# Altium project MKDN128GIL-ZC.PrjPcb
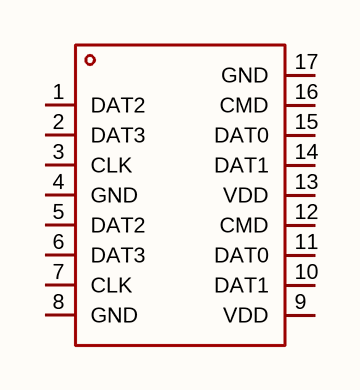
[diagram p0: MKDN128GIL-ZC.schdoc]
1 sheet, 1 parts. Net scope: global (net labels, ports and power ports of the same name join across sheets).

## Sheet MKDN128GIL-ZC.schdoc
size 127 x 101 mm

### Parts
U?  mkdn128gil-zc  [LGA-16_L13.0-W9.0_MKDN128GIL-ZC]  (value not drawn)

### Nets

Not connected (* = marked no-connect by the designer): U? 1(DAT2) 2(DAT3) 3(CLK) 4(GND) 5(DAT2) 6(DAT3) 7(CLK) 8(GND) 9(VDD) 10(DAT1) 11(DAT0) 12(CMD) 13(VDD) 14(DAT1) 15(DAT0) 16(CMD) 17(GND)

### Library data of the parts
U? = mkdn128gil-zc: 存储容量:128Gbit;时钟频率(fc):208MHz;工作电压:2.7V~3.6V;; Manufacturer: MK(米客方德); AddInBom: yes; ModelId: cec9fa0b07e3433dbfbc5ad139c7f3fa; ModelTransform: 511.81,354.33,0,0,0,0,0,0,0; Interface: SD接口; Clock Frequency: 208MHz; Standby Supply Current: 70uA; ECC: 有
